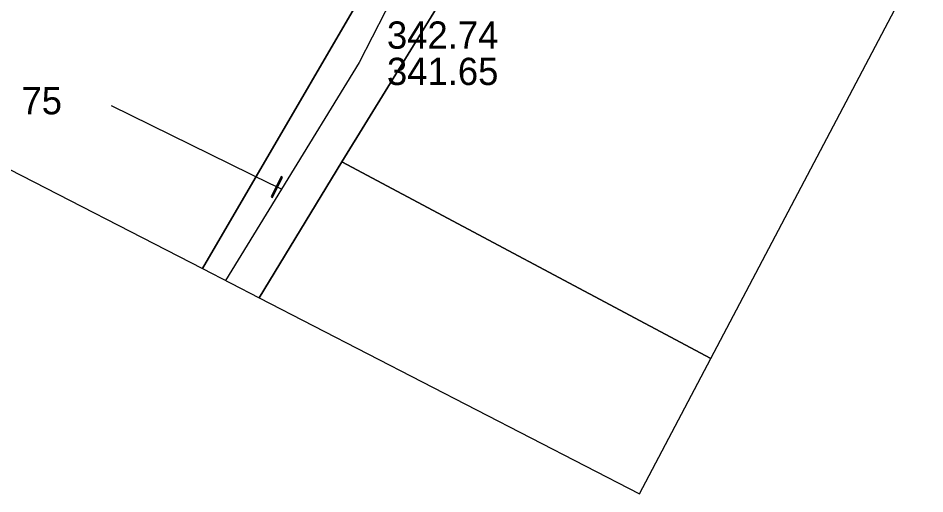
# Model space of a CAD drawing. Extents: x -559654 to -559448, y -1076607 to -1076478.
# Drawn here: x -559511.05 to -559461.14, y -1076606.86 to -1076580.66 of the extents above; entities that cross this region are included whole.
import ezdxf

# ---------------------------------------------------------------- set-up
doc = ezdxf.new("R2010")
doc.units = 0
for name, color, linetype in [('Armatura vodovodní', 7, 'Continuous'), ('Parcela-polygon', 7, 'Continuous'), ('Parcela-text', 7, 'Continuous'), ('Popis šachty', 7, 'Continuous'), ('Vodovodní přípojka', 7, 'Continuous'), ('Vodovodní řad', 7, 'Continuous')]:
    doc.layers.add(name, color=color, linetype=linetype)

msp = doc.modelspace()

# ---------------------------------------------------------------- linework, layer by layer
at = {"layer": 'Armatura vodovodní'}
msp.add_lwpolyline([(-559497.056, -1076590.537), (-559496.505, -1076589.415), (-559496.575, -1076589.381), (-559497.126, -1076590.503)], close=True, dxfattribs=at)
at = {"layer": 'Parcela-polygon'}
for p, q in [((-559472.923, -1076599.402), (-559461.138, -1076577.031)), ((-559515.683, -1076586.846), (-559500.912, -1076594.458)), ((-559500.912, -1076594.458), (-559497.784, -1076596.071))]:
    msp.add_line(p, q, dxfattribs=at)
for points in [[(-559470.396, -1076542.745), (-559478.68, -1076557.2), (-559485.32, -1076568.19), (-559489.07, -1076574.14), (-559500.912, -1076594.458)], [(-559497.784, -1076596.071), (-559493.23, -1076588.57), (-559485.49, -1076575.98), (-559482.14, -1076570.54), (-559468.14, -1076545.12), (-559467.515, -1076544.007)], [(-559500.912, -1076594.458), (-559489.07, -1076574.14), (-559505.11, -1076565.7), (-559515.683, -1076586.846)], [(-559461.138, -1076577.031), (-559476.74, -1076568.93), (-559481.94, -1076577.8), (-559485.49, -1076575.98), (-559493.23, -1076588.57), (-559472.923, -1076599.402)], [(-559472.923, -1076599.402), (-559493.23, -1076588.57), (-559497.784, -1076596.071)], [(-559497.784, -1076596.071), (-559476.851, -1076606.859), (-559472.923, -1076599.402)]]:
    msp.add_lwpolyline(points, dxfattribs=at)
at = {"layer": 'Vodovodní přípojka'}
msp.add_lwpolyline([(-559496.554, -1076590.087), (-559496.815, -1076589.96), (-559497.176, -1076589.782), (-559505.918, -1076585.49)], dxfattribs=at)
at = {"layer": 'Vodovodní řad'}
msp.add_lwpolyline([(-559485.627, -1076570.145), (-559488.697, -1076576.122), (-559492.285, -1076583.109), (-559496.554, -1076590.087), (-559499.632, -1076595.118)], dxfattribs=at)

# ---------------------------------------------------------------- texts
at = {"layer": 'Parcela-text'}
msp.add_text('75', height=1.5, dxfattribs=at).set_placement((-559510.87, -1076585.96))
at = {"layer": 'Popis šachty'}
for s, p in [('342.74', (-559490.75, -1076582.346)), ('341.65', (-559490.75, -1076584.346))]:
    msp.add_text(s, height=1.5, dxfattribs=at).set_placement(p)

doc.saveas('drawing.dxf')
